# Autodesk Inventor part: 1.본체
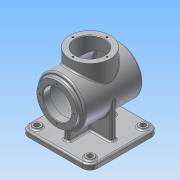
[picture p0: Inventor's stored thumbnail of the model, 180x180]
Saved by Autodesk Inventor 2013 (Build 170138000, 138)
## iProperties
Created: 2015-07
Part Number: 1.본체
Material: 알루미늄 6061
Document SubType Name: Modeling
Designer: Administrator
Density: 2.71 g/cm^3
Mass: 1372.97 g
Surface Area: 1250.05 cm^2
Volume: 506.633 cm^3
Author: Administrator
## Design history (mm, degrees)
sketch "스케치1"
  geometry: L1 (-50, 65)-(50, 65); L2 (65, 50)-(65, -50); L3 (50, -65)-(-50, -65); L4 (-65, -50)-(-65, 50); A1 r 15 centre (50, 50) between (65, 50) and (50, 65); A2 r 15 centre (50, -50) between (50, -65) and (65, -50); A3 r 15 centre (-50, -50) between (-65, -50) and (-50, -65); A4 r 15 centre (-50, 50) between (-50, 65) and (-65, 50); 3 further points
  constraints: 8 end point, 8 point on circle, 8 tangent, 4 centre point, 3 equal radius, 2 midpoint, 2 parallel, 2 perpendicular, 1 horizontal, 1 horizontal alignment, 1 vertical alignment
  dimensions: "d1" = 130 distance between parallel lines of L2 L4; "d3" = 15 radius of A1
extrude "돌출1" new body sketch "스케치1" distance "d4" = 10; taper "d5" = 0 deg
sketch "스케치2"
  geometry: L1 (-50, 0)-(50, 0) reference; C1 r 45 at (0, 78); 2 further points
  constraints: 1 centre point, 1 midpoint, 1 vertical alignment
  dimensions: "d6" = 78 distance from line of C1.centre L1; "d7" = 90 diameter of C1
extrude "돌출2" join sketch "스케치2" stored distance "d8" = 110; taper "d9" = 0 deg
sketch "스케치3"
  geometry: L1 (50, -78)-(-50, -78) reference; C1 r 45 at (0, 0) reference; C2 r 38 at (0, 0); 1 further point
  constraints: 1 centre point, 1 coincident
  dimensions: "d10" = 76 diameter of C2
extrude "돌출3" join sketch "스케치3" distance "d12" = 7; taper "d13" = 0 deg
node "작업 평면1"
sketch "스케치5"
  geometry: C1 r 38 at (0, 0); 1 further point
  constraints: 1 centre point, 1 coincident
  dimensions: "d15" = 76 diameter of C1
extrude "돌출4" join sketch "스케치5" distance "d17" = 62; taper "d18" = 0 deg
sketch "스케치7"
  geometry: C1 r 27 at (0, 0); 1 further point
  constraints: 1 centre point, 1 coincident
  dimensions: "d24" = 54 diameter of C1
extrude "돌출5" cut sketch "스케치7" distance "d26" = 62; taper "d27" = 0 deg
sketch "스케치8" dims "d28" = 64
  geometry: 3 further points
  constraints: 2 horizontal alignment, 1 coincident, 2 other
hole "구멍1" sketch "스케치8" at (-32, 0) diameter "d30" = 3.242; stored, may be unused: countersink angle "d34" = 90 deg, drill point angle "d36" = 118 deg; dims "d31" = 8, "d32" = 4, "d33" = 2, "d35" = 10
sketch "스케치9"
  geometry: L1 (-5, 45)-(5, 45); L2 (5, -45)-(-5, -45); L3 (45, 5)-(45, -5); L4 (-45, -5)-(-45, 5); L5 (5, 45)-(5, 5); L6 (5, -5)-(5, -45); L7 (-45, 5)-(-5, 5); L8 (5, 5)-(45, 5); L9 (-5, -45)-(-5, -5); L10 (-5, 5)-(-5, 45); L11 (45, -5)-(5, -5); L12 (-5, -5)-(-45, -5); 3 further points
  constraints: 24 end point, 10 parallel, 4 collinear, 4 perpendicular, 3 horizontal, 2 midpoint, 1 horizontal alignment, 1 vertical alignment
  dimensions: "d40" = 10 distance between parallel lines of L5 L10; "d42" = 10 distance between parallel lines of L11 L8; "d43" = 90 distance between parallel lines of L3 L4; "d44" = 90 distance between parallel lines of L2 L1; "d45" = 45 distance from line of L3 point (0, 0); "d46" = 45 distance from line of L2 point (0, 0)
extrude "돌출6" join sketch "스케치9" distance "d47" = 68; taper "d48" = 0 deg
sketch "스케치10"
  geometry: L1 (-62, 116)-(-62, 40) reference; L2 (55, 33)-(55, 123) reference; L3 (-62, 78)-(48, 78); L4 (-62, 105)-(-48, 105); L5 (-48, 105)-(-48, 118); L6 (-48, 118)-(48, 118); L7 (48, 118)-(48, 78); 1 further point
  constraints: 10 end point, 2 parallel, 2 perpendicular, 1 midpoint, 1 point on line
  dimensions: "d49" = 7 distance between parallel lines of L2 L7; "d50" = 54 diameter of L4 L3; "d51" = 80 diameter of L6 L3; "d52" = 14 distance between parallel lines of L5 L1
revolve "회전2" sketch "스케치10" stored, may be unused: angle "d53" = 90 deg
sketch "스케치11" dims "d54" = 64
  geometry: C1 r 38 at (0, 0) reference; 3 further points
  constraints: 2 vertical alignment, 1 coincident, 2 other
hole "구멍2" sketch "스케치11" at (0, 32) diameter "d56" = 3.242; stored, may be unused: countersink angle "d60" = 90 deg, drill point angle "d62" = 118 deg; dims "d57" = 8, "d58" = 4, "d59" = 2, "d61" = 10
sketch "스케치12"
  geometry: C1 r 7.5 at (50, 50); C2 r 7.5 at (-50, 50); C3 r 7.5 at (-50, -50); C4 r 7.5 at (50, -50); 1 further point
  constraints: 4 centre point, 3 equal radius, 2 horizontal alignment, 2 vertical alignment
  dimensions: "d66" = 100 distance of C4.centre C1.centre; "d68" = 100 distance of C1.centre C2.centre; "d69" = 50 horizontal distance of C1.centre point (0, 0); "d70" = 50 horizontal distance of C1.centre point (0, 0); "d71" = 15 diameter of C2
extrude "돌출7" join sketch "스케치12" distance "d74" = 3; taper "d75" = 0 deg
hole "구멍3" diameter "d78" = 10; stored, may be unused: countersink angle "d82" = 90 deg, drill point angle "d84" = 118 deg; dims "d76" = 10, "d77" = 10, "d79" = 10, "d80" = 4, "d81" = 2, "d83" = 10
hole "구멍4" diameter "d87" = 10; stored, may be unused: countersink angle "d91" = 90 deg, drill point angle "d93" = 118 deg; dims "d85" = 10, "d86" = 10, "d88" = 10, "d89" = 4, "d90" = 2, "d92" = 10
hole "구멍5" diameter "d96" = 10; stored, may be unused: countersink angle "d100" = 90 deg, drill point angle "d102" = 118 deg; dims "d94" = 10, "d95" = 10, "d97" = 10, "d98" = 4, "d99" = 2, "d101" = 10
hole "구멍6" diameter "d105" = 10; stored, may be unused: countersink angle "d109" = 90 deg, drill point angle "d111" = 118 deg; dims "d103" = 10, "d104" = 10, "d106" = 10, "d107" = 4, "d108" = 2, "d110" = 10
sketch "스케치14"
  geometry: L1 (24.887, -3.602)-(-24.887, -3.602); L2 (-24.887, -3.602)-(-24.887, 3.602); L3 (-24.887, 3.602)-(24.887, 3.602); L4 (24.887, 3.602)-(24.887, -3.602); A1 r 45 centre (0, 0) between (45, 0) and (5, 44.721) reference; A2 r 45 centre (0, 0) between (5, 44.721) and (-5, 44.721) reference; A3 r 45 centre (0, 0) between (-5, 44.721) and (-45, 0) reference; A4 r 45 centre (0, 0) between (45, 0) and (5, 44.721) reference; 6 further points
  constraints: 4 midpoint, 2 horizontal alignment, 2 vertical alignment, 1 coincident, 2 other
feature "엠보싱1" sketch "스케치14" dims "d112" = 0.5, "d113" = 0
chamfer "모따기1" distance "d114" = 1; stored, may be unused: second distance "d115" = 2, angle "d116" = 45 deg
fillet "모깎기1" dims "d117" = 3
fillet "모깎기2" dims "d118" = 3
fillet "모깎기3" dims "d119" = 3
fillet "모깎기4" dims "d120" = 3
fillet "모깎기5" dims "d121" = 3
fillet "모깎기6" dims "d122" = 3
fillet "모깎기7" dims "d123" = 3
fillet "모깎기8" dims "d124" = 3
node "솔리드1"
pattern_circular "원형 패턴1" dims angle "d38" = 360 deg
pattern_circular "원형 패턴2" dims angle "d64" = 360 deg
other parameters: "d14" = 78
